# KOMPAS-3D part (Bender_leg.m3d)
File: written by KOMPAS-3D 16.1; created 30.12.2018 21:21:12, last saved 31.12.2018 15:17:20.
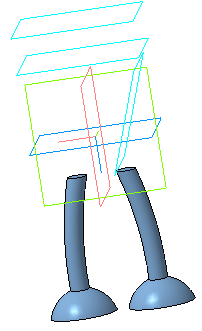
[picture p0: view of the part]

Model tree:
1. Эскиз:1
2. Операция вращения:1
     Угол 1 = 360
3. Эскиз:2
4. Операция выдавливания:1
     Расстояние 1 = 17.3; Угол 1 = 0.45
5. Скругление:1
     Радиус = 0.5
6. Скругление:2
     Радиус = 5
7. Смещенная плоскость:1
     Расстояние = 48
8. Эскиз:3
9. Вырезать элемент выдавливания:1
     Расстояние 1 = 10
10. Скругление:3
     Радиус = 5
11. Эскиз:4
12. Вырезать элемент выдавливания:2
     Расстояние 1 = 0.5
13. Эскиз:5
14. Операция вращения:2
     Угол 1 = 360
15. Эскиз:6
16. Операция вращения:3
     Угол 1 = 360
17. Эскиз:7
18. Эскиз:8
19. Кинематическая операция:1
20. Эскиз:9
21. Операция вращения:4
     Угол 1 = 360
22. Эскиз:10
23. Перпендикулярная плоскость:1
24. Эскиз:11
25. Кинематическая операция:2
26. Эскиз:12
27. Операция выдавливания:3
     Расстояние 1 = 7; Угол 1 = 20; Расстояние 2 = 0.5
28. Эскиз:13
29. Операция выдавливания:4
     Расстояние 1 = 7; Расстояние 2 = 0.5
30. Скругление:4
     Радиус = 2
31. Зеркальный массив:1
32. Экземпляр ( 1 )
33. Экземпляр ( 2 )  (with: Кинематическая операция:1, Операция вращения:4, Кинематическая операция:2, Операция выдавливания:3, Операция выдавливания:4, Скругление:4)
34. Смещенная плоскость:2
     Расстояние = 33
35. Сечение поверхностью:1
36. Сечение поверхностью:2
37. Эскиз:14
38. Вырезать элемент выдавливания:3
     Расстояние 1 = 20

Referenced files in C:\Users\NIK\Desktop\: bender_bending_rodriguez_3d_model_c4d_max_obj_fbx_ma_lwo_3ds_3dm_stl_1135635_o.png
